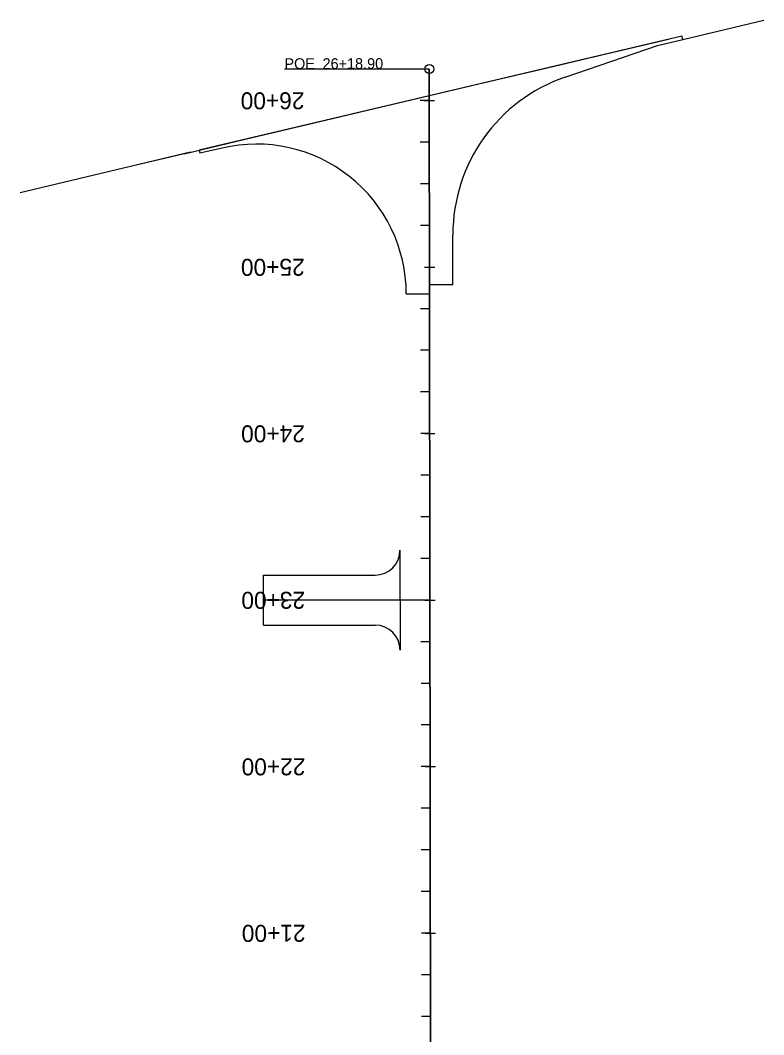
# Model space of a CAD drawing. Extents: x 18438067 to 18438528, y 7650200 to 7651853.
# Drawn here: x 18438067 to 18438513, y 7651244 to 7651853 of the extents above; entities that cross this region are included whole.
import ezdxf

# ---------------------------------------------------------------- set-up
doc = ezdxf.new("R2010")
doc.units = 0
for name, color, linetype in [('_CIVIL_CONSTRUCTION', 7, 'Continuous'), ('Draft_DNC', 7, 'Continuous'), ('EdgePaved', 7, 'Continuous'), ('EdgeUnpaved', 7, 'Continuous'), ('Section Lines', 7, 'Continuous'), ('TC_Granular', 7, 'Continuous'), ('TextAlignment', 7, 'Continuous'), ('TextAlignmentLrg', 7, 'Continuous'), ('TextAlignmentSml', 7, 'Continuous')]:
    doc.layers.add(name, color=color, linetype=linetype)

msp = doc.modelspace()

# ---------------------------------------------------------------- linework, layer by layer
at = {"layer": '_CIVIL_CONSTRUCTION'}
for p, q in [((18438313.08, 7651225.86), (18438312.27, 7651823.56)), ((18438312.7, 7651504.65), (18438212.7, 7651504.65))]:
    msp.add_line(p, q, dxfattribs=at)
at = {"layer": 'Draft_DNC'}
for p, q in [((18438464.42, 7651841.37), (18438513.08, 7651852.85)), ((18438312.45, 7651688.63), (18438312.29, 7651807.55)), ((18438312.45, 7651688.63), (18438312.29, 7651807.55)), ((18438168.88, 7651773.68), (18438066.63, 7651749.13)), ((18438326.44, 7651693.93), (18438312.44, 7651693.91)), ((18438298.45, 7651688.61), (18438312.45, 7651688.63))]:
    msp.add_line(p, q, dxfattribs=at)
at = {"layer": 'EdgePaved'}
for p, q in [((18438463.95, 7651843.35), (18438173.98, 7651774.9)), ((18438449.25, 7651837.79), (18438464.42, 7651841.37)), ((18438464.42, 7651841.37), (18438463.95, 7651843.35)), ((18438393.84, 7651818.71), (18438449.25, 7651837.79)), ((18438173.98, 7651774.9), (18438174.44, 7651772.95)), ((18438187.9, 7651776.11), (18438174.44, 7651772.95)), ((18438326.44, 7651693.93), (18438326.4, 7651724.02))]:
    msp.add_line(p, q, dxfattribs=at)
for centre, radius, start, end in [((18438426.4, 7651724.16), 100, 109.00231, 180.07767), ((18438426.4, 7651724.16), 100, 109.00231, 180.07767), ((18438208.45, 7651688.49), 90, 0.07765, 103.20069)]:
    msp.add_arc(centre, radius, start, end, dxfattribs=at)
at = {"layer": 'EdgeUnpaved'}
msp.add_line((18438294.66, 7651534.65), (18438294.74, 7651474.65), dxfattribs=at)
at = {"layer": 'Section Lines'}
for p, q in [((18438212.68, 7651519.54), (18438279.68, 7651519.63)), ((18438294.7, 7651504.65), (18438212.7, 7651504.65)), ((18438212.72, 7651489.54), (18438279.72, 7651489.63))]:
    msp.add_line(p, q, dxfattribs=at)
for centre, start, end in [((18438279.66, 7651534.63), 270.07765, 0.07765), ((18438279.74, 7651474.63), 0.07765, 90.07765)]:
    msp.add_arc(centre, 15, start, end, dxfattribs=at)
at = {"layer": 'TC_Granular'}
for p, q in [((18438312.27, 7651823.56), (18438313.32, 7651045.51)), ((18438313.32, 7651045.51), (18438312.27, 7651823.56))]:
    msp.add_line(p, q, dxfattribs=at)
at = {"layer": 'TextAlignment'}
msp.add_line((18438312.27, 7651823.56), (18438225.27, 7651823.44), dxfattribs=at)
msp.add_circle((18438312.27, 7651823.56), 2.67, dxfattribs=at)
at = {"layer": 'TextAlignmentLrg'}
for p, q in [((18438312.29, 7651804.65), (18438306.83, 7651804.65)), ((18438309.37, 7651704.65), (18438315.49, 7651704.66)), ((18438312.56, 7651604.65), (18438307.1, 7651604.65)), ((18438312.7, 7651504.65), (18438307.24, 7651504.65)), ((18438312.83, 7651404.65), (18438307.37, 7651404.65)), ((18438312.97, 7651304.66), (18438307.51, 7651304.65))]:
    msp.add_line(p, q, dxfattribs=at)
at = {"layer": 'TextAlignmentSml'}
for p, q in [((18438309.23, 7651804.65), (18438315.35, 7651804.66)), ((18438312.32, 7651779.65), (18438306.86, 7651779.65)), ((18438164.99, 7651772.74), (18438138.8, 7651766.46)), ((18438312.36, 7651754.65), (18438306.9, 7651754.65)), ((18438312.39, 7651729.65), (18438306.93, 7651729.65)), ((18438309.37, 7651704.65), (18438315.49, 7651704.66)), ((18438312.46, 7651679.65), (18438307, 7651679.65)), ((18438312.49, 7651654.65), (18438307.03, 7651654.65)), ((18438312.53, 7651629.65), (18438307.07, 7651629.65)), ((18438309.5, 7651604.65), (18438315.62, 7651604.66)), ((18438312.6, 7651579.65), (18438307.14, 7651579.65)), ((18438312.63, 7651554.65), (18438307.17, 7651554.65)), ((18438312.66, 7651529.65), (18438307.2, 7651529.65)), ((18438212.72, 7651489.54), (18438212.68, 7651519.54)), ((18438309.64, 7651504.65), (18438315.76, 7651504.66)), ((18438312.73, 7651479.65), (18438307.27, 7651479.65)), ((18438312.77, 7651454.65), (18438307.31, 7651454.65)), ((18438312.8, 7651429.65), (18438307.34, 7651429.65)), ((18438309.77, 7651404.65), (18438315.89, 7651404.66)), ((18438312.87, 7651379.65), (18438307.41, 7651379.65)), ((18438312.9, 7651354.65), (18438307.44, 7651354.65)), ((18438312.93, 7651329.65), (18438307.47, 7651329.65)), ((18438309.91, 7651304.65), (18438316.03, 7651304.66)), ((18438313, 7651279.66), (18438307.54, 7651279.65)), ((18438313.04, 7651254.66), (18438307.58, 7651254.65))]:
    msp.add_line(p, q, dxfattribs=at)
msp.add_lwpolyline([(18438164.99, 7651772.74), (18438201.61, 7651781.53), (18438238.82, 7651790.26), (18438275.1, 7651798.81), (18438312.31, 7651807.61), (18438348.79, 7651816.19), (18438383.11, 7651824.29), (18438419.29, 7651832.89), (18438455.86, 7651841.46)], dxfattribs=at)

# ---------------------------------------------------------------- texts
at = {"layer": 'TextAlignment'}
for s, p in [('POE ', (18438225.27, 7651823.55)), ('26+18.90', (18438248.17, 7651823.58))]:
    msp.add_text(s, height=6.48, rotation=0.07765, dxfattribs=at).set_placement(p)
at = {"layer": 'TextAlignmentLrg'}
msp.add_text('25+00', height=10.2, rotation=180.07765, dxfattribs=at).set_placement((18438237.42, 7651709.65))
at = {"layer": 'TextAlignmentSml'}
for s, p in [('26+00', (18438237.28, 7651809.65)), ('25+00', (18438237.42, 7651709.65)), ('24+00', (18438237.55, 7651609.65)), ('23+00', (18438237.69, 7651509.65)), ('22+00', (18438237.83, 7651409.65)), ('21+00', (18438237.96, 7651309.65))]:
    msp.add_text(s, height=10.2, rotation=180.07765, dxfattribs=at).set_placement(p)

doc.saveas('drawing.dxf')
